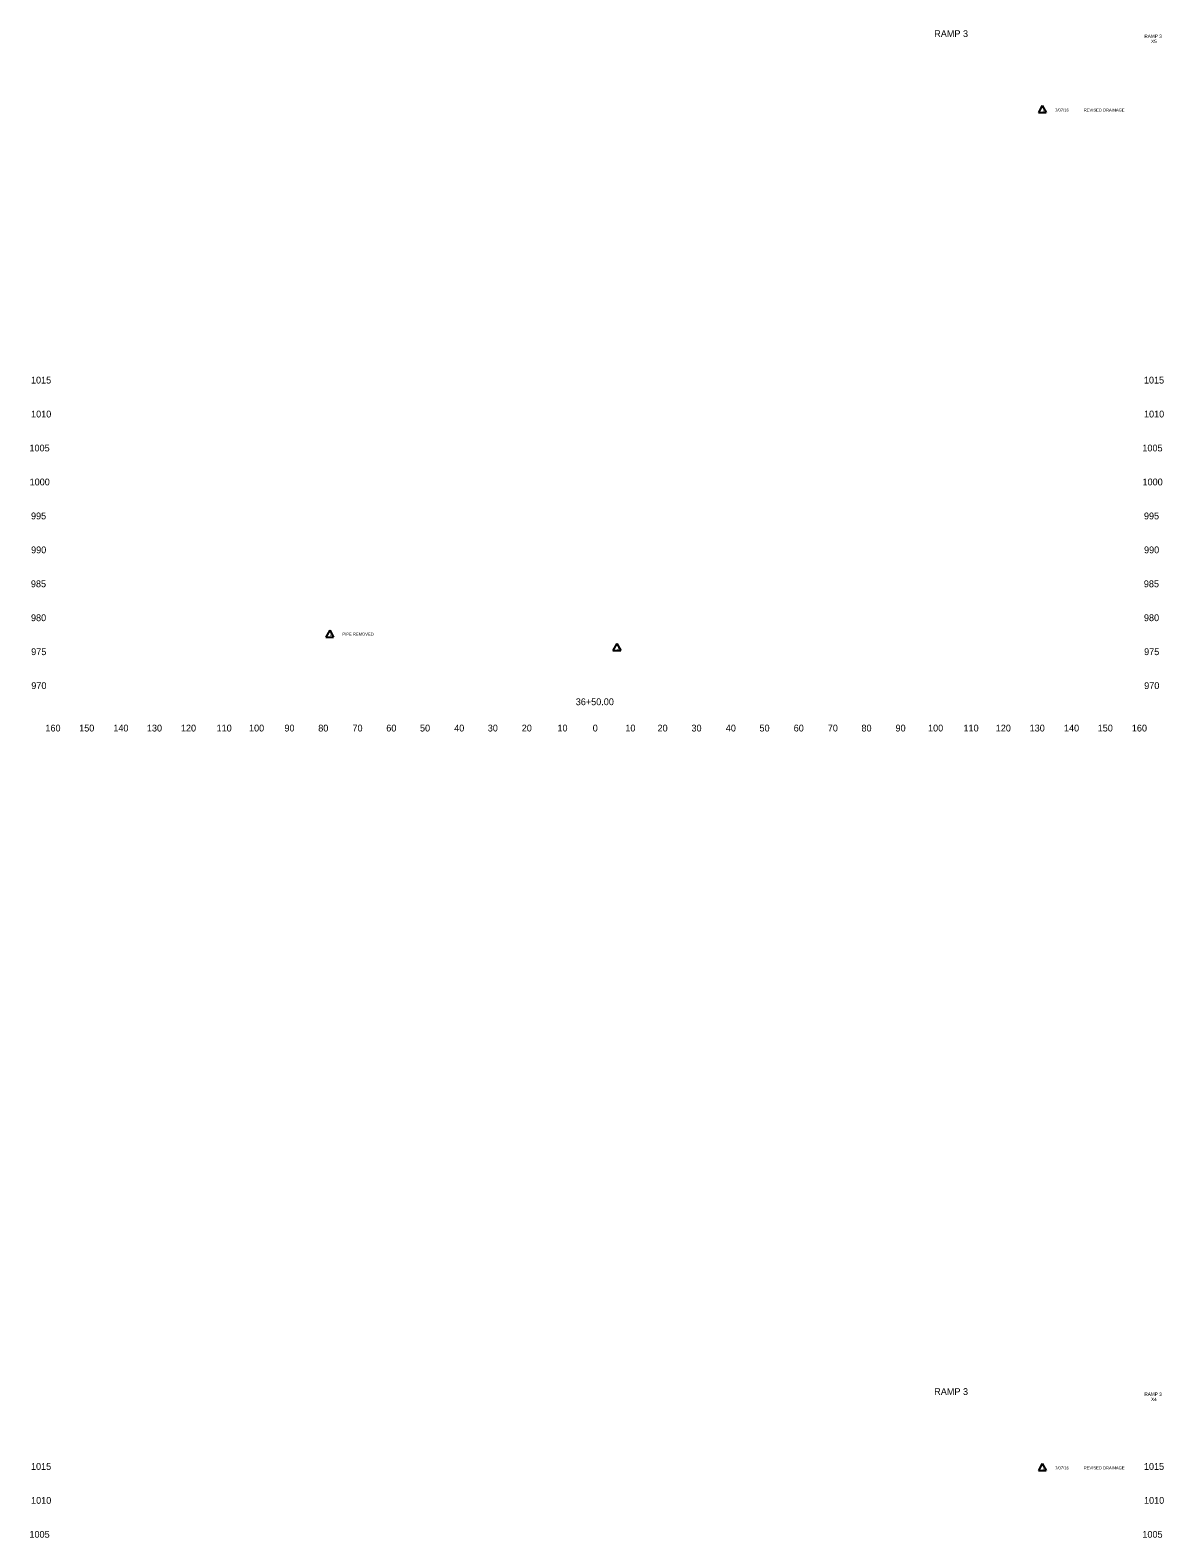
# Model space of a CAD drawing. Extents: x 4994 to 5843, y 4997 to 8804.
# Drawn here: x 4993.6 to 5327.5, y 6360 to 6804.1 of the extents above; entities that cross this region are included whole.
import ezdxf

# ---------------------------------------------------------------- set-up
doc = ezdxf.new("R2010")
doc.units = 0
for name, color, linetype in [('RD_SHT_ID', 7, 'Continuous'), ('RD_SHT_TX', 7, 'Continuous'), ('RD_XS_TX_Offset', 7, 'Continuous'), ('RD_XS_TX_Station', 7, 'Continuous')]:
    doc.layers.add(name, color=color, linetype=linetype)

msp = doc.modelspace()

# ---------------------------------------------------------------- linework, layer by layer
at = {"layer": 'RD_SHT_TX'}
for p, q in [((5291.7, 6781.86), (5290.56, 6779.83)), ((5291.7, 6781.86), (5292.84, 6779.83)), ((5290.56, 6779.83), (5292.84, 6779.83)), ((5081.84, 6627.35), (5080.7, 6625.32)), ((5081.84, 6627.35), (5082.97, 6625.32)), ((5080.7, 6625.32), (5082.97, 6625.32)), ((5166.41, 6623.38), (5165.27, 6621.35)), ((5166.41, 6623.38), (5167.55, 6621.35)), ((5165.27, 6621.35), (5167.55, 6621.35)), ((5291.7, 6381.86), (5290.56, 6379.83)), ((5290.56, 6379.83), (5292.84, 6379.83)), ((5291.7, 6381.86), (5292.84, 6379.83))]:
    msp.add_line(p, q, dxfattribs=at)

# ---------------------------------------------------------------- texts
at = {"layer": 'RD_SHT_ID'}
for s, height, p in [('RAMP 3', 2, (5259.89, 6802.06)), ('RAMP 3', 1, (5321.78, 6801.8)), ('X5', 1, (5323.74, 6800.3)), ('RAMP 3', 2, (5259.89, 6402.06)), ('RAMP 3', 1, (5321.78, 6401.8)), ('X4', 1, (5323.74, 6400.3))]:
    msp.add_text(s, height=height, dxfattribs=at).set_placement(p)
at = {"layer": 'RD_SHT_TX'}
for s, p in [('1', (5291.7, 6780.16)), ('7/07/16', (5295.48, 6780.12)), ('REVISED DRAINAGE', (5303.93, 6780.12)), ('1', (5081.84, 6625.65)), ('PIPE REMOVED', (5085.55, 6625.74)), ('1', (5166.41, 6621.68)), ('1', (5291.7, 6380.16)), ('7/07/16', (5295.48, 6380.12)), ('REVISED DRAINAGE', (5303.93, 6380.12))]:
    msp.add_text(s, height=0.88, dxfattribs=at).set_placement(p)
at = {"layer": 'RD_XS_TX_Offset'}
for s, p in [('1015', (4993.85, 6700)), ('1015', (5321.65, 6700)), ('1010', (4993.88, 6690)), ('1010', (5321.68, 6690)), ('1005', (4993.4, 6680)), ('1005', (5321.2, 6680)), ('1000', (4993.44, 6670)), ('1000', (5321.24, 6670)), ('995', (4993.86, 6660)), ('995', (5321.66, 6660)), ('990', (4993.89, 6650)), ('990', (5321.69, 6650)), ('985', (4993.83, 6640)), ('985', (5321.63, 6640)), ('980', (4993.86, 6630)), ('980', (5321.66, 6630)), ('975', (4993.91, 6620)), ('975', (5321.71, 6620)), ('970', (4993.94, 6610)), ('970', (5321.74, 6610)), ('160', (4998.1, 6597.5)), ('150', (5008.04, 6597.5)), ('140', (5018.1, 6597.5)), ('130', (5027.99, 6597.5)), ('120', (5038.01, 6597.5)), ('110', (5048.51, 6597.5)), ('100', (5058.07, 6597.5)), ('90', (5068.5, 6597.5)), ('80', (5078.46, 6597.5)), ('70', (5088.54, 6597.5)), ('60', (5098.5, 6597.5)), ('50', (5108.43, 6597.5)), ('40', (5118.5, 6597.5)), ('30', (5128.39, 6597.5)), ('20', (5138.4, 6597.5)), ('10', (5148.91, 6597.5)), ('0', (5159.3, 6597.5)), ('0', (5159.3, 6597.5)), ('10', (5168.91, 6597.5)), ('20', (5178.4, 6597.5)), ('30', (5188.39, 6597.5)), ('40', (5198.5, 6597.5)), ('50', (5208.43, 6597.5)), ('60', (5218.5, 6597.5)), ('70', (5228.54, 6597.5)), ('80', (5238.46, 6597.5)), ('90', (5248.5, 6597.5)), ('100', (5258.07, 6597.5)), ('110', (5268.51, 6597.5)), ('120', (5278.01, 6597.5)), ('130', (5287.99, 6597.5)), ('140', (5298.1, 6597.5)), ('150', (5308.04, 6597.5)), ('160', (5318.1, 6597.5)), ('1015', (4993.85, 6380)), ('1015', (5321.65, 6380)), ('1010', (4993.88, 6370)), ('1010', (5321.68, 6370)), ('1005', (4993.4, 6360)), ('1005', (5321.2, 6360))]:
    msp.add_text(s, height=2, dxfattribs=at).set_placement(p)
at = {"layer": 'RD_XS_TX_Station'}
msp.add_text('36+50.00', height=2, dxfattribs=at).set_placement((5154.31, 6605.25))

doc.saveas('drawing.dxf')
